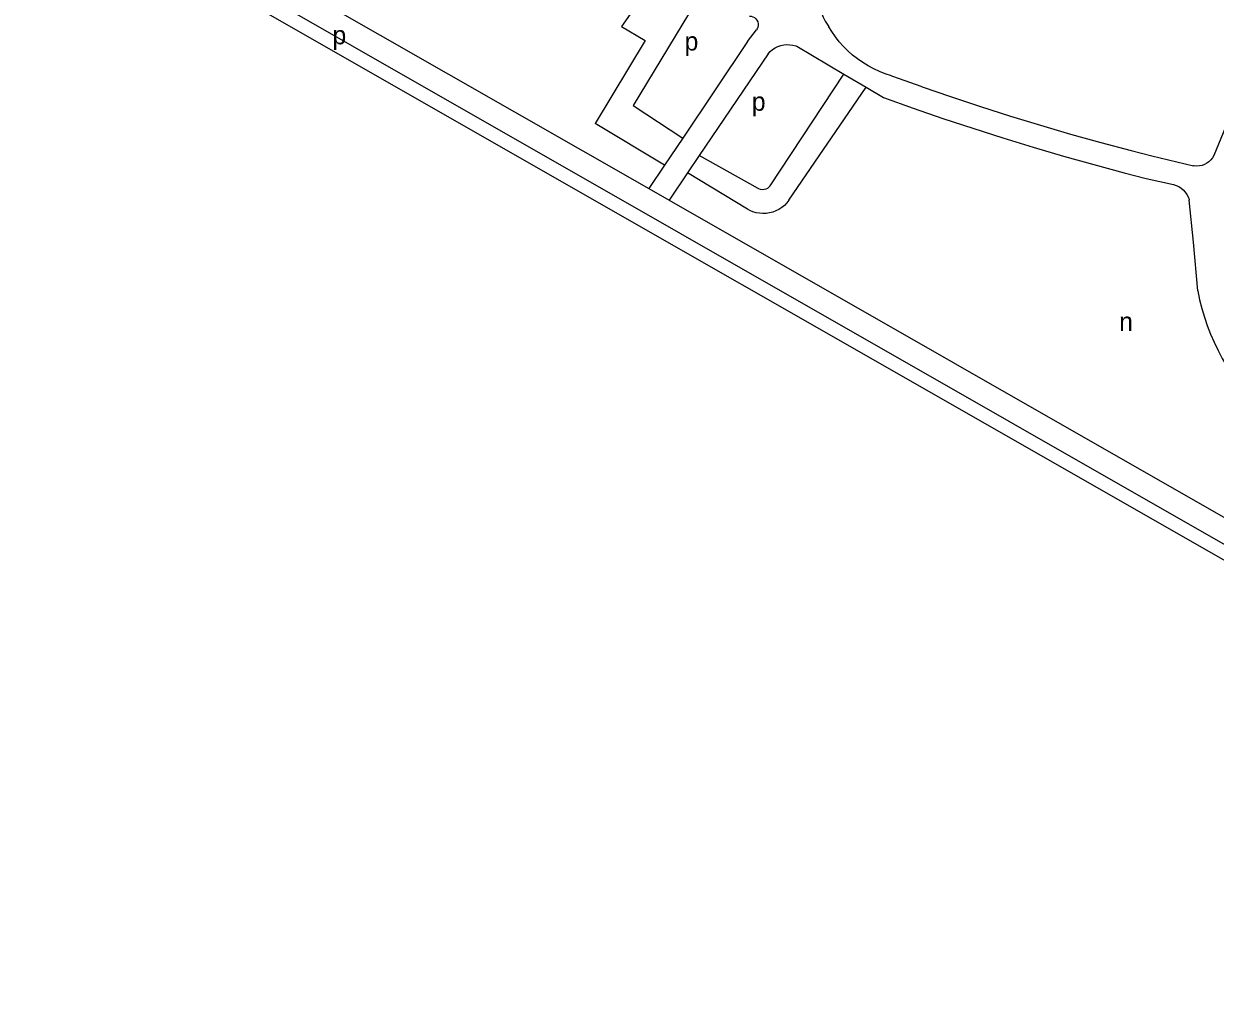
# Model space of a CAD drawing. Extents: x 157155 to 159285, y 385001 to 386651.
# Drawn here: x 158523 to 158780.5, y 385069 to 385278.4 of the extents above; entities that cross this region are included whole.
import ezdxf

# ---------------------------------------------------------------- set-up
doc = ezdxf.new("R2010")
doc.units = 0
for name, color, linetype in [('BLT_Basislijn', 7, 'Continuous'), ('BLT_Centroide', 7, 'Continuous'), ('BLT_Vlakafsluiter', 7, 'Continuous')]:
    doc.layers.add(name, color=color, linetype=linetype)

msp = doc.modelspace()

# ---------------------------------------------------------------- linework, layer by layer
at = {"layer": 'BLT_Basislijn'}
for p, q in [((158524.7, 385319), (158658.07, 385242.8)), ((158523.9, 385310.24), (158946.21, 385068.98)), ((158679.39, 385274.55), (158681.36, 385277.12)), ((158657.28, 385274.76), (158646.45, 385256.83)), ((158679.39, 385274.55), (158665.39, 385253.7)), ((158690.05, 385273.54), (158700.24, 385267.53)), ((158683.83, 385271.92), (158668.94, 385249.94)), ((158684.27, 385243.39), (158700.24, 385267.53)), ((158700.24, 385267.53), (158705.04, 385264.69)), ((158710.48, 385267.18), (158712.2, 385266.57)), ((158688.31, 385240.29), (158705.04, 385264.69)), ((158705.04, 385264.69), (158708.77, 385262.49)), ((158661.46, 385247.85), (158646.45, 385256.83)), ((158783.22, 385257.3), (158780.15, 385249.92)), ((158665.39, 385253.7), (158661.46, 385247.85)), ((158668.94, 385249.94), (158666.44, 385246.24)), ((158681.73, 385242.81), (158668.94, 385249.94)), ((158766.79, 385249.85), (158775.8, 385247.74)), ((158661.46, 385247.85), (158658.07, 385242.8)), ((158666.44, 385246.24), (158662.43, 385240.32)), ((158679.39, 385238.35), (158666.44, 385246.24)), ((158765.56, 385245), (158771.45, 385243.7)), ((158662.43, 385240.32), (158951.28, 385075.3))]:
    msp.add_line(p, q, dxfattribs=at)
for points in [[(158522.97, 385314.23), (158948.8, 385070.96), (158946.21, 385068.98)], [(158695.01, 385287.56), (158694.83, 385286.59), (158694.73, 385285.6), (158694.71, 385284.62), (158694.76, 385283.63), (158694.9, 385282.65), (158695.11, 385281.69), (158695.4, 385280.75), (158695.77, 385279.83), (158696.21, 385278.95), (158696.72, 385278.1), (158696.97, 385277.75)], [(158669.71, 385285.67), (158654.67, 385260.78), (158665.39, 385253.7)], [(158655.03, 385281.93), (158652.17, 385277.81), (158657.28, 385274.76)], [(158679.81, 385280.08), (158680.19, 385280.04), (158680.56, 385279.92), (158680.9, 385279.73), (158681.19, 385279.47), (158681.42, 385279.16), (158681.59, 385278.81), (158681.68, 385278.43), (158681.68, 385278.05), (158681.62, 385277.67), (158681.47, 385277.31), (158681.36, 385277.12)], [(158710.48, 385267.18), (158709.18, 385267.61), (158707.92, 385268.11), (158706.68, 385268.68), (158705.48, 385269.32), (158704.31, 385270.03), (158703.19, 385270.81), (158702.12, 385271.66), (158701.1, 385272.56), (158700.14, 385273.52), (158699.23, 385274.54), (158698.38, 385275.61), (158697.6, 385276.73), (158696.97, 385277.75)], [(158683.83, 385271.92), (158684.28, 385272.41), (158684.79, 385272.83), (158685.35, 385273.19), (158685.94, 385273.49), (158686.57, 385273.7), (158687.22, 385273.85), (158687.88, 385273.91), (158688.54, 385273.89), (158689.2, 385273.79), (158689.84, 385273.62), (158690.05, 385273.54)], [(158712.2, 385266.57), (158716.88, 385264.9), (158717.12, 385264.81)], [(158717.12, 385264.81), (158723.3, 385262.68), (158729.74, 385260.54), (158736.22, 385258.48), (158742.71, 385256.49), (158749.23, 385254.58), (158755.77, 385252.75), (158762.33, 385251), (158766.79, 385249.85)], [(158708.77, 385262.49), (158715.19, 385260.19), (158721.64, 385257.96), (158728.11, 385255.82), (158734.61, 385253.74), (158741.14, 385251.75), (158747.68, 385249.83), (158754.25, 385247.98), (158760.84, 385246.22), (158765.56, 385245)], [(158780.15, 385249.92), (158779.88, 385249.43), (158779.53, 385248.98), (158779.13, 385248.59), (158778.67, 385248.26), (158778.18, 385248), (158777.65, 385247.81), (158777.1, 385247.7), (158776.53, 385247.66), (158775.97, 385247.71), (158775.8, 385247.74)], [(158684.27, 385243.39), (158684.03, 385243.09), (158683.73, 385242.85), (158683.38, 385242.67), (158683.01, 385242.57), (158682.62, 385242.54), (158682.23, 385242.6), (158681.87, 385242.73), (158681.73, 385242.81)], [(158771.45, 385243.7), (158772.04, 385243.5), (158772.6, 385243.24), (158773.11, 385242.9), (158773.58, 385242.5), (158773.99, 385242.04), (158774.35, 385241.54), (158774.63, 385240.99), (158774.84, 385240.41), (158774.87, 385240.28)], [(158688.31, 385240.29), (158687.87, 385239.71), (158687.36, 385239.18), (158686.79, 385238.72), (158686.18, 385238.32), (158685.53, 385237.98), (158684.85, 385237.72), (158684.14, 385237.54), (158683.42, 385237.43), (158682.69, 385237.41), (158681.96, 385237.46), (158681.24, 385237.6), (158680.54, 385237.81), (158679.87, 385238.09), (158679.39, 385238.35)], [(158776.73, 385220.7), (158775.8, 385231.26), (158774.87, 385240.28)], [(158776.73, 385220.7), (158777.12, 385218.79), (158777.59, 385216.9), (158778.14, 385215.04), (158778.77, 385213.2), (158779.46, 385211.38), (158780.24, 385209.59), (158781.09, 385207.84), (158782, 385206.13), (158782.85, 385204.68)]]:
    msp.add_lwpolyline(points, dxfattribs=at)
at = {"layer": 'BLT_Vlakafsluiter'}
msp.add_line((158658.07, 385242.8), (158662.43, 385240.32), dxfattribs=at)

# ---------------------------------------------------------------- texts
at = {"layer": 'BLT_Centroide'}
for s, p in [('p', (158589.68, 385273.97)), ('p', (158665.79, 385272.63)), ('p', (158680.32, 385259.62)), ('n', (158759.72, 385212.07))]:
    msp.add_text(s, height=4, dxfattribs=at).set_placement(p)

doc.saveas('drawing.dxf')
